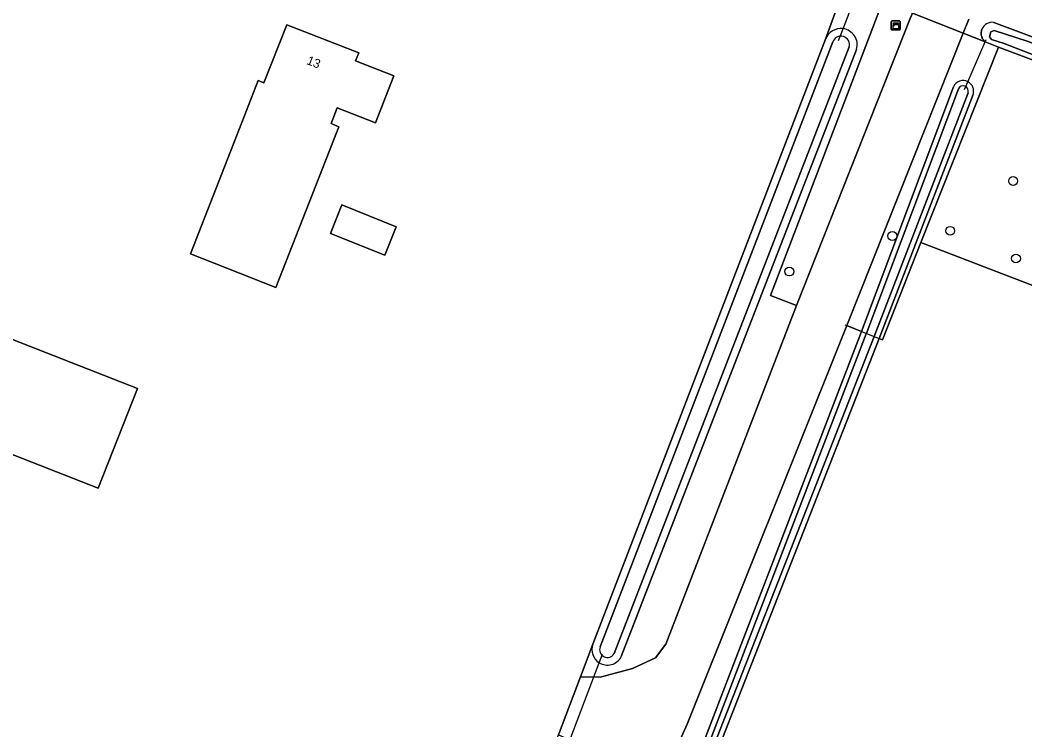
# Model space of a CAD drawing. Extents: x 155209 to 156748, y 385356 to 388487.
# Drawn here: x 155768.7 to 155880.6, y 386589.2 to 386668.2 of the extents above; entities that cross this region are included whole.
import ezdxf

# ---------------------------------------------------------------- set-up
doc = ezdxf.new("R2010")
doc.units = 0
for name, color, linetype in [('IMGEO_Boom', 7, 'Continuous'), ('IMGEO_Bouwland', 7, 'Continuous'), ('IMGEO_Duiker', 7, 'Continuous'), ('IMGEO_Erf', 7, 'Continuous'), ('IMGEO_Grasland_overig', 7, 'Continuous'), ('IMGEO_Groenvoorziening', 7, 'Continuous'), ('IMGEO_Haag', 7, 'Continuous'), ('IMGEO_Hek', 7, 'Continuous'), ('IMGEO_Kast', 7, 'Continuous'), ('IMGEO_Oever', 7, 'Continuous'), ('IMGEO_Pand', 7, 'Continuous'), ('IMGEO_Pand_nummerreeks', 7, 'Continuous'), ('IMGEO_Rijbaan_lokaal_open', 7, 'Continuous'), ('IMGEO_Waterloop', 7, 'Continuous')]:
    doc.layers.add(name, color=color, linetype=linetype)

msp = doc.modelspace()

# ---------------------------------------------------------------- linework, layer by layer
at = {"layer": 'IMGEO_Boom'}
for centre in [(155879.27, 386650.3), (155865.82, 386644.18), (155872.27, 386644.76), (155879.59, 386641.67), (155854.35, 386640.21)]:
    msp.add_circle(centre, 0.489, dxfattribs=at)
at = {"layer": 'IMGEO_Bouwland'}
for points in [[(155902.97, 386655.71), (155877.65, 386665.23), (155869.01, 386643.44), (155965.82, 386606.23), (155974.96, 386627.94)], [(155920.62, 386500), (155949.82, 386568.26), (155965.82, 386606.23), (155869.01, 386643.44), (155864.71, 386632.61), (155864.34, 386632.76), (155844.68, 386582.56), (155842.49, 386576.7), (155812.69, 386500), (155808.11, 386488.2), (155808.11, 386488.16), (155806.31, 386482.13), (155806.23, 386481.98), (155776.16, 386404.85), (155770.45, 386390.2), (155742.01, 386316.6), (155739.62, 386308.66), (155823.47, 386270.87), (155882.29, 386410.38)]]:
    msp.add_lwpolyline(points, close=True, dxfattribs=at)
at = {"layer": 'IMGEO_Duiker'}
for points in [[(155859.83, 386665.97), (155860.33, 386667.27), (155861.92, 386671.39), (155862.29, 386672.35)], [(155873.86, 386660.48), (155874.24, 386661.36), (155876.16, 386665.82), (155876.27, 386666.06)], [(155828.8, 386585.14), (155829.07, 386585.85), (155833.17, 386596.64), (155833.53, 386597.6)]]:
    msp.add_lwpolyline(points, dxfattribs=at)
at = {"layer": 'IMGEO_Erf'}
msp.add_lwpolyline([(155827.24, 386584.98), (155828.63, 386588.62), (155831.1, 386595.08), (155832.48, 386598.7), (155858.39, 386666.09), (155860.17, 386671.06), (155845.78, 386676.56), (155815.75, 386688.47), (155811.53, 386686.69), (155808.55, 386689.62), (155807.95, 386691.6), (155784.6, 386700.46), (155766.42, 386707.35), (155764.8, 386707.96), (155764.04, 386705.95)], dxfattribs=at)
for points in [[(155793.38, 386656.83), (155795.21, 386661.48), (155795.84, 386661.24), (155798.38, 386667.71), (155806.4, 386664.57), (155806.05, 386663.69), (155810.31, 386662.02), (155808.26, 386656.8), (155804.01, 386658.47), (155803.31, 386656.69), (155804.19, 386656.35), (155802.36, 386651.69), (155797.17, 386638.44), (155787.64, 386642.18)], [(155803.24, 386644.46), (155804.52, 386647.64), (155810.57, 386645.21), (155809.29, 386642.03)], [(155749.51, 386627.01), (155753.88, 386638.1), (155781.74, 386627.17), (155777.39, 386616.07)]]:
    msp.add_lwpolyline(points, close=True, dxfattribs=at)
at = {"layer": 'IMGEO_Grasland_overig'}
msp.add_lwpolyline([(155843.12, 386583.39), (155862.38, 386633.54), (155860.74, 386634.19), (155842.99, 386589.8), (155837.24, 386577.02), (155807.91, 386500), (155780.04, 386426.8), (155770.92, 386403.12), (155764.64, 386405.34), (155770.07, 386419.5)], dxfattribs=at)
at = {"layer": 'IMGEO_Groenvoorziening'}
msp.add_lwpolyline([(155867.81, 386668.39), (155868.05, 386669), (155863.85, 386670.65), (155861.92, 386671.39), (155860.5, 386671.92), (155860.17, 386671.06), (155864.42, 386669.44), (155852.27, 386637.56), (155855.14, 386636.42)], close=True, dxfattribs=at)
for points in [[(155855.14, 386636.42), (155852.27, 386637.56), (155864.42, 386669.44), (155860.17, 386671.06), (155858.39, 386666.09)], [(155874.34, 386668.32), (155873.72, 386666.78), (155876.16, 386665.82), (155876.08, 386665.9), (155876, 386665.98), (155875.94, 386666.06), (155875.88, 386666.15), (155875.83, 386666.25), (155875.79, 386666.35), (155875.76, 386666.46), (155875.73, 386666.56), (155875.72, 386666.67), (155875.72, 386666.78), (155875.72, 386666.89), (155875.74, 386666.99), (155875.77, 386667.1), (155875.8, 386667.2)], [(155877.11, 386667.97), (155902.84, 386658.33), (156000, 386620.97), (156034.05, 386607.74), (156040.24, 386604.88), (156046.53, 386602.9), (156080.99, 386589.91), (156096.99, 386583.72), (156123.14, 386574.02), (156129.81, 386571.56), (156135.61, 386569.52), (156137.2, 386568.86), (156137.88, 386568.44), (156138.05, 386567.68), (156138.04, 386567.52), (156138.02, 386566.69), (156137.76, 386565.73), (156137.44, 386565.47), (156138.21, 386565.19)], [(155877.65, 386665.23), (155876.16, 386665.82), (155873.72, 386666.78), (155860.74, 386634.19), (155862.38, 386633.54), (155872.64, 386660.8)], [(155861.84, 386664.97), (155835.62, 386597.32)], [(155874.81, 386659.93), (155864.34, 386632.76), (155864.71, 386632.61), (155869.01, 386643.44), (155877.65, 386665.23)], [(155832.48, 386598.7), (155831.1, 386595.08), (155833.27, 386595.02), (155834.97, 386595.48), (155836.9, 386595.99), (155839.46, 386597.18), (155840.59, 386598.69), (155855.14, 386636.42)]]:
    msp.add_lwpolyline(points, dxfattribs=at)
for centre, radius, start, end in [((155876.94, 386666.76), 1.22, 81.7074, 158.5606), ((155860.09, 386665.47), 1.82, 82.4618, 160.0441), ((155860.09, 386665.47), 1.82, 344.0883, 82.4136), ((155873.7, 386660.32), 1.17, 62.6929, 155.8364), ((155873.71, 386660.32), 1.17, 340.5752, 62.7236), ((155834.09, 386598.09), 1.72, 159.3186, 237.4844), ((155834.09, 386598.09), 1.72, 237.5754, 333.0217)]:
    msp.add_arc(centre, radius, start, end, dxfattribs=at)
at = {"layer": 'IMGEO_Haag'}
msp.add_lwpolyline([(155867.81, 386668.39), (155868.05, 386669), (155863.85, 386670.65), (155861.92, 386671.39), (155860.5, 386671.92), (155860.17, 386671.06), (155864.42, 386669.44), (155852.27, 386637.56), (155855.14, 386636.42)], close=True, dxfattribs=at)
for points in [[(155877.65, 386665.23), (155876.16, 386665.82), (155873.72, 386666.78), (155860.74, 386634.19), (155862.38, 386633.54), (155872.64, 386660.8)], [(155874.81, 386659.93), (155864.34, 386632.76), (155864.71, 386632.61), (155869.01, 386643.44), (155877.65, 386665.23)]]:
    msp.add_lwpolyline(points, dxfattribs=at)
for centre, start, end in [((155873.7, 386660.32), 62.6929, 155.8364), ((155873.71, 386660.32), 340.5752, 62.7236)]:
    msp.add_arc(centre, 1.17, start, end, dxfattribs=at)
at = {"layer": 'IMGEO_Hek'}
for points in [[(155864.34, 386632.76), (155864.71, 386632.61), (155869.01, 386643.44), (155877.65, 386665.23)], [(155860.54, 386634.27), (155862.38, 386633.54)], [(155862.38, 386633.54), (155864.34, 386632.76)]]:
    msp.add_lwpolyline(points, dxfattribs=at)
at = {"layer": 'IMGEO_Kast'}
for p, q in [((155865.7, 386667.21), (155865.7, 386668.05)), ((155865.7, 386668.05), (155865.7, 386667.21)), ((155865.78, 386668.13), (155866.62, 386668.13)), ((155866.62, 386668.13), (155865.78, 386668.13)), ((155866.7, 386668.06), (155866.7, 386667.22)), ((155866.7, 386667.22), (155866.7, 386668.06)), ((155866.63, 386667.13), (155865.79, 386667.13)), ((155865.79, 386667.13), (155866.63, 386667.13))]:
    msp.add_line(p, q, dxfattribs=at)
for points in [[(155865.9, 386667.92), (155866.5, 386667.92), (155866.5, 386667.84), (155865.9, 386667.84), (155865.9, 386667.92)], [(155865.9, 386667.75), (155866.5, 386667.75), (155866.5, 386667.26), (155865.9, 386667.26), (155865.9, 386667.75)]]:
    msp.add_lwpolyline(points, dxfattribs=at)
msp.add_circle((155865.98, 386667.6), 0.0377, dxfattribs=at)
for centre, start, end in [((155865.78, 386668.05), 92.4484, 184.2845), ((155865.78, 386668.05), 92.4484, 184.2845), ((155866.62, 386668.05), 2.4484, 94.2845), ((155866.62, 386668.05), 2.4484, 94.2845), ((155865.78, 386667.21), 182.4484, 274.2845), ((155865.78, 386667.21), 182.4484, 274.2845), ((155866.62, 386667.21), 272.4484, 4.2845), ((155866.62, 386667.21), 272.4484, 4.2845)]:
    msp.add_arc(centre, 0.0779, start, end, dxfattribs=at)
at = {"layer": 'IMGEO_Oever'}
for points in [[(155876.16, 386665.82), (155877.65, 386665.23), (155902.97, 386655.71), (155974.96, 386627.94), (155978.88, 386626.57), (156000, 386618.39), (156032.82, 386605.78), (156033.86, 386606), (156034.11, 386606.65), (156034.05, 386607.74), (156000, 386620.97), (155902.84, 386658.33), (155877.11, 386667.97)], [(155875.8, 386667.2), (155875.77, 386667.1), (155875.74, 386666.99), (155875.72, 386666.89), (155875.72, 386666.78), (155875.72, 386666.67), (155875.73, 386666.56), (155875.76, 386666.46), (155875.79, 386666.35), (155875.83, 386666.25), (155875.88, 386666.15), (155875.94, 386666.06), (155876, 386665.98), (155876.08, 386665.9), (155876.16, 386665.82)], [(155858.39, 386666.09), (155832.48, 386598.7)], [(155833.28, 386598.4), (155859.19, 386665.79)], [(155861.03, 386665.24), (155834.84, 386597.67)], [(155835.62, 386597.32), (155861.84, 386664.97)], [(155872.64, 386660.8), (155862.38, 386633.54), (155843.12, 386583.39)], [(155843.67, 386583.14), (155862.92, 386633.26), (155862.93, 386633.28), (155862.93, 386633.29), (155862.94, 386633.31), (155862.98, 386633.39), (155863, 386633.47), (155863.03, 386633.55), (155873.19, 386660.57)], [(155874.25, 386660.14), (155863.79, 386632.98), (155844.15, 386582.85)], [(155864.34, 386632.76), (155874.81, 386659.93)], [(155844.68, 386582.56), (155864.34, 386632.76)]]:
    msp.add_lwpolyline(points, dxfattribs=at)
msp.add_lwpolyline([(155978.55, 386628.3), (155998.68, 386620.6), (156025.49, 386610.28), (156033.43, 386607.18), (156033.46, 386606.83), (156033.21, 386606.53), (156023.95, 386609.9), (155994.44, 386621.24), (155977.43, 386627.53), (155948.06, 386638.91), (155928.66, 386646.46), (155896.95, 386658.35), (155878.29, 386665.62), (155876.85, 386666.07), (155876.64, 386666.35), (155876.8, 386666.93), (155877.15, 386667.08), (155880.96, 386665.86), (155899.45, 386658.52), (155928.33, 386647.56), (155962.66, 386634.35)], close=True, dxfattribs=at)
for centre, radius, start, end in [((155876.94, 386666.76), 1.22, 81.7074, 158.5606), ((155860.09, 386665.47), 1.82, 82.4618, 160.0441), ((155860.09, 386665.47), 1.82, 344.0883, 82.4136), ((155860.09, 386665.47), 0.964, 346.0559, 160.3861), ((155873.7, 386660.32), 1.17, 62.6929, 155.8364), ((155873.71, 386660.32), 1.17, 340.5752, 62.7236), ((155873.71, 386660.32), 0.574, 340.9316, 154.7974), ((155834.09, 386598.09), 1.72, 159.3186, 237.4844), ((155834.09, 386598.09), 0.864, 159.3832, 330.7276), ((155834.09, 386598.09), 1.72, 237.5754, 333.0217)]:
    msp.add_arc(centre, radius, start, end, dxfattribs=at)
at = {"layer": 'IMGEO_Pand'}
for points in [[(155806.05, 386663.69), (155806.4, 386664.57), (155798.38, 386667.71), (155795.84, 386661.24), (155795.21, 386661.48), (155793.38, 386656.83), (155787.64, 386642.18), (155797.17, 386638.44), (155802.36, 386651.69), (155804.19, 386656.35), (155803.31, 386656.69), (155804.01, 386658.47), (155808.26, 386656.8), (155810.31, 386662.02)], [(155803.24, 386644.46), (155809.29, 386642.03), (155810.57, 386645.21), (155804.52, 386647.64)], [(155777.39, 386616.07), (155781.74, 386627.17), (155753.88, 386638.1), (155749.51, 386627.01)]]:
    msp.add_lwpolyline(points, close=True, dxfattribs=at)
at = {"layer": 'IMGEO_Rijbaan_lokaal_open'}
msp.add_lwpolyline([(155868.42, 386669.95), (155868.05, 386669), (155873.72, 386666.78), (155874.34, 386668.32)], dxfattribs=at)
msp.add_lwpolyline([(155860.74, 386634.19), (155873.72, 386666.78), (155868.05, 386669), (155867.81, 386668.39), (155855.14, 386636.42), (155840.59, 386598.69), (155839.46, 386597.18), (155836.9, 386595.99), (155834.97, 386595.48), (155833.27, 386595.02), (155831.1, 386595.08), (155828.63, 386588.62), (155830.35, 386587.85), (155831.32, 386586.8), (155832.62, 386584.62), (155834.05, 386581.94), (155834.21, 386580.97), (155834.03, 386579.78), (155833.54, 386578.47), (155837.24, 386577.02), (155842.99, 386589.8)], close=True, dxfattribs=at)
at = {"layer": 'IMGEO_Waterloop'}
msp.add_lwpolyline([(155978.55, 386628.3), (155962.66, 386634.35), (155928.33, 386647.56), (155899.45, 386658.52), (155880.96, 386665.86), (155877.15, 386667.08), (155876.8, 386666.93), (155876.64, 386666.35), (155876.85, 386666.07), (155878.29, 386665.62), (155896.95, 386658.35), (155928.66, 386646.46), (155948.06, 386638.91), (155977.43, 386627.53), (155994.44, 386621.24), (156023.95, 386609.9), (156033.21, 386606.53), (156033.46, 386606.83), (156033.43, 386607.18), (156025.49, 386610.28), (155998.68, 386620.6)], close=True, dxfattribs=at)
for points in [[(155859.19, 386665.79), (155833.28, 386598.4)], [(155834.84, 386597.67), (155861.03, 386665.24)], [(155873.19, 386660.57), (155863.03, 386633.55), (155863, 386633.47), (155862.98, 386633.39), (155862.94, 386633.31), (155862.93, 386633.29), (155862.93, 386633.28), (155862.92, 386633.26), (155843.67, 386583.14)], [(155844.15, 386582.85), (155863.79, 386632.98), (155874.25, 386660.14)]]:
    msp.add_lwpolyline(points, dxfattribs=at)
for centre, radius, start, end in [((155860.09, 386665.47), 0.964, 346.0559, 160.3861), ((155873.71, 386660.32), 0.574, 340.9316, 154.7974), ((155834.09, 386598.09), 0.864, 159.3832, 330.7276)]:
    msp.add_arc(centre, radius, start, end, dxfattribs=at)

# ---------------------------------------------------------------- texts
at = {"layer": 'IMGEO_Pand_nummerreeks'}
msp.add_text('13', height=1, rotation=338.579, dxfattribs=at).set_placement((155800.51, 386663.35))

doc.saveas('drawing.dxf')
